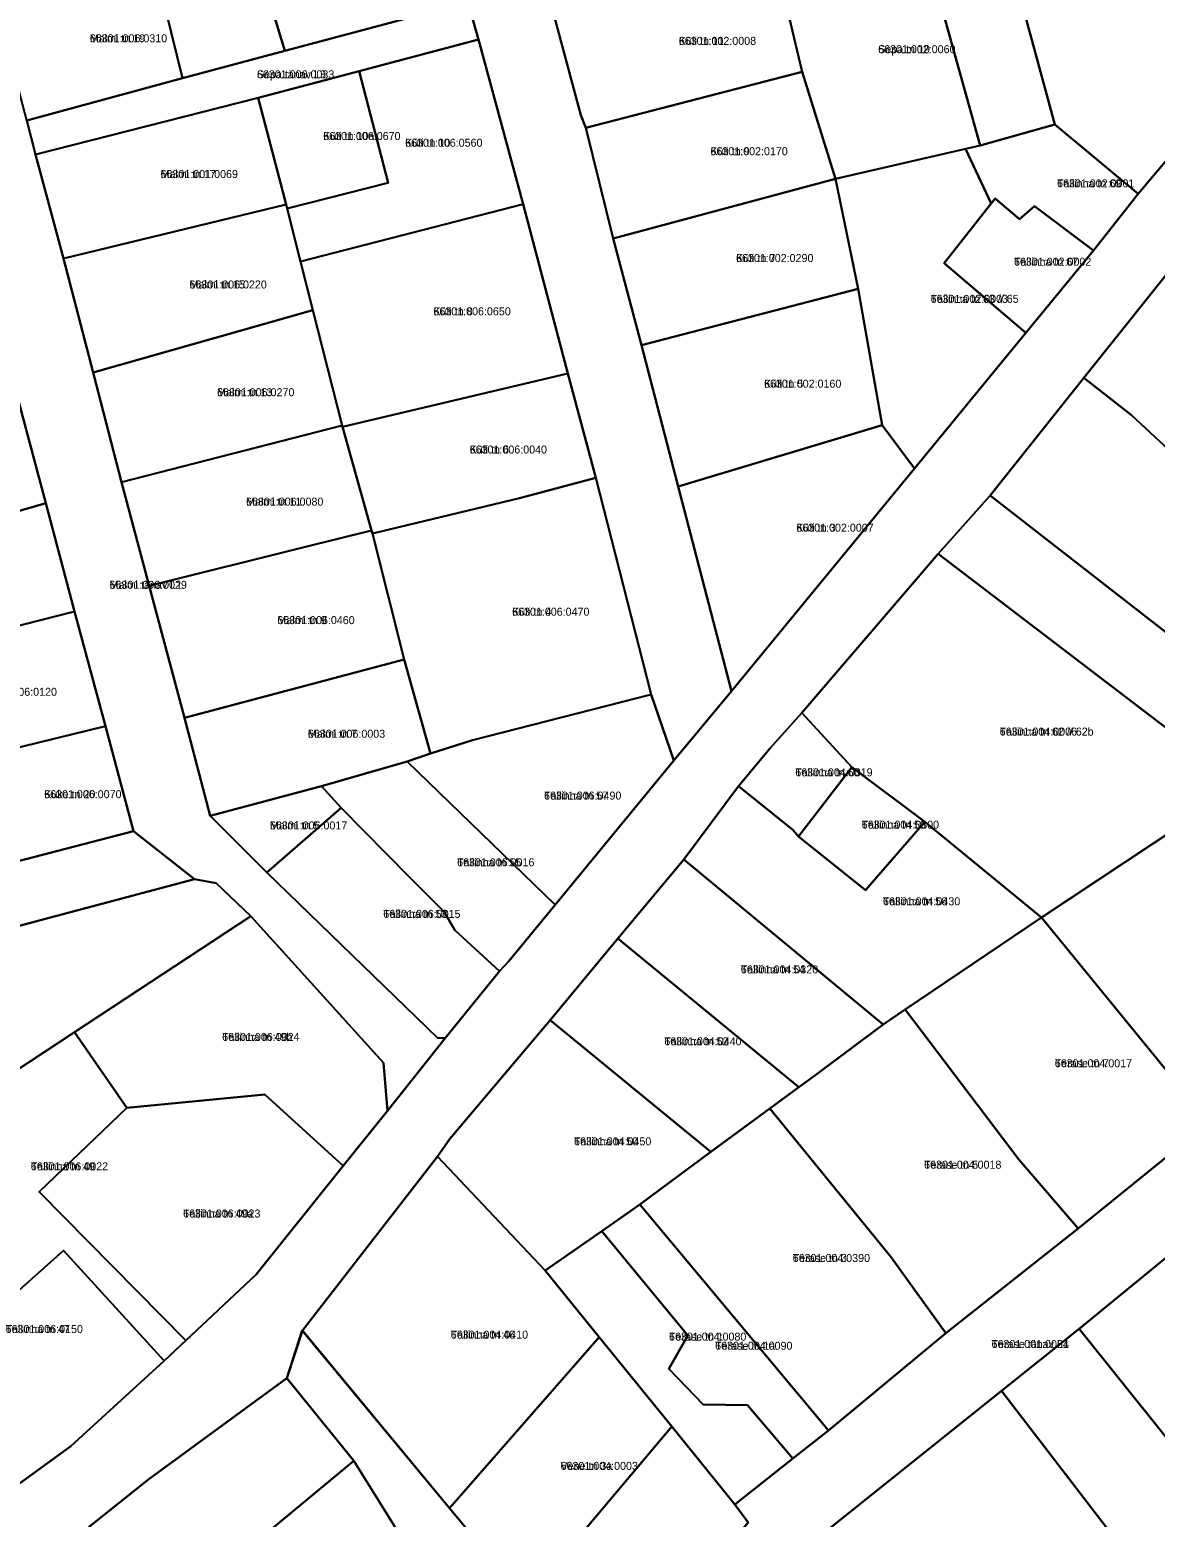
# Model space of a CAD drawing. Extents: x 632278 to 636344, y 6578401 to 6583362.
# Drawn here: x 634433.6 to 634644.7, y 6581866.9 to 6582145.8 of the extents above; entities that cross this region are included whole.
import ezdxf

# ---------------------------------------------------------------- set-up
doc = ezdxf.new("R2010")
doc.units = 0
for name, color, linetype in [('L_AADRESS', 7, 'Continuous'), ('PIIR', 7, 'Continuous'), ('TUNNUS', 7, 'Continuous')]:
    doc.layers.add(name, color=color, linetype=linetype)

msp = doc.modelspace()

# ---------------------------------------------------------------- linework, layer by layer
at = {"layer": 'PIIR'}
for points in [[(634482.01, 6582273.84), (634497.33, 6582277.18), (634507.5, 6582238.54), (634524.92, 6582174.47), (634530.36, 6582154.21), (634536.9, 6582129.81), (634537.89, 6582127.43), (634543.01, 6582106.64), (634548.28, 6582086.63), (634555.2, 6582060.13), (634565.22, 6582021.79), (634554.37, 6582008.75), (634550.12, 6582021.16), (634539.75, 6582061.77), (634534.51, 6582081.35), (634526.1, 6582113.12), (634517.75, 6582143.96), (634515.75, 6582150.96), (634510.3, 6582170.19), (634506.82, 6582183.37), (634504.01, 6582193.51), (634492.92, 6582234.47)], [(634515.75, 6582150.96), (634481.42, 6582141.82), (634475.39, 6582161.69), (634510.3, 6582170.19)], [(634600.44, 6582164.99), (634614.08, 6582168.85), (634619.66, 6582150.78), (634625.82, 6582128.04), (634611.81, 6582124.08)], [(634611.81, 6582124.08), (634584.7, 6582117.84), (634578.42, 6582137.89), (634573.58, 6582158.48), (634600.44, 6582164.99)], [(634456.96, 6582158.09), (634463.95, 6582159.56), (634468.75, 6582160.65), (634475.39, 6582161.69), (634481.42, 6582141.82), (634462.21, 6582136.73)], [(634456.96, 6582158.09), (634462.21, 6582136.73), (634433, 6582128.78), (634427.44, 6582149.82)], [(634532.03, 6582147.94), (634573.58, 6582158.48), (634578.42, 6582137.89), (634537.89, 6582127.43), (634536.9, 6582129.81)], [(634625.82, 6582128.04), (634619.66, 6582150.78), (634634.35, 6582155.12), (634643.77, 6582154.58), (634670.18, 6582151.52), (634667.16, 6582146.78), (634653.84, 6582129.72), (634641.46, 6582115.05)], [(634433, 6582128.78), (634462.21, 6582136.73), (634481.42, 6582141.82), (634515.75, 6582150.96), (634517.75, 6582143.96), (634495.33, 6582138.01), (634476.44, 6582133.05), (634434.65, 6582122.42)], [(634481.87, 6582112.27), (634500.78, 6582117.12), (634495.33, 6582138.01), (634517.75, 6582143.96), (634526.1, 6582113.12), (634484.38, 6582102.35)], [(634481.67, 6582113.05), (634476.44, 6582133.05), (634495.33, 6582138.01), (634500.78, 6582117.12), (634481.87, 6582112.27)], [(634537.89, 6582127.43), (634578.42, 6582137.89), (634584.7, 6582117.84), (634543.01, 6582106.64)], [(634439.93, 6582102.93), (634434.65, 6582122.42), (634476.44, 6582133.05), (634481.67, 6582113.05)], [(634613.87, 6582113.21), (634609.09, 6582123.45), (634611.81, 6582124.08), (634625.82, 6582128.04), (634641.46, 6582115.05), (634633.11, 6582104.43), (634622.05, 6582112.71), (634619.2, 6582110.28), (634614.63, 6582114.15)], [(634584.7, 6582117.84), (634609.09, 6582123.45), (634613.87, 6582113.21), (634605.06, 6582102.02), (634620.38, 6582088.96), (634599.5, 6582063.53), (634593.46, 6582071.65), (634588.97, 6582097.23)], [(634543.01, 6582106.64), (634584.7, 6582117.84), (634588.97, 6582097.23), (634548.28, 6582086.63)], [(634620.38, 6582088.96), (634605.06, 6582102.02), (634613.87, 6582113.21), (634614.63, 6582114.15), (634619.2, 6582110.28), (634622.05, 6582112.71), (634633.11, 6582104.43)], [(634481.87, 6582112.27), (634484.38, 6582102.35), (634486.69, 6582093.22), (634445.48, 6582081.5), (634439.93, 6582102.93), (634481.67, 6582113.05)], [(634492.23, 6582071.37), (634492.18, 6582071.58), (634486.69, 6582093.22), (634484.38, 6582102.35), (634526.1, 6582113.12), (634534.51, 6582081.35)], [(634650.44, 6582104.55), (634665.94, 6582089.46), (634671.9, 6582071.57), (634666.84, 6582067.2), (634665.01, 6582065.62), (634677.33, 6582051.32), (634679.16, 6582052.92), (634684.17, 6582057.32), (634699.78, 6582060.69), (634682.62, 6582038.21), (634666.05, 6582050.23), (634653.33, 6582061.35), (634640.2, 6582073.51), (634631.3, 6582080.56)], [(634588.97, 6582097.23), (634593.46, 6582071.65), (634555.2, 6582060.13), (634548.28, 6582086.63)], [(634445.48, 6582081.5), (634486.69, 6582093.22), (634492.18, 6582071.58), (634450.77, 6582060.94)], [(634497.64, 6582051.91), (634492.23, 6582071.37), (634534.51, 6582081.35), (634539.75, 6582061.77), (634525.44, 6582057.97), (634497.83, 6582051.33)], [(634613.71, 6582058.49), (634631.3, 6582080.56), (634640.2, 6582073.51), (634653.33, 6582061.35), (634666.05, 6582050.23), (634682.62, 6582038.21), (634665.06, 6582018.52)], [(634390.13, 6582066.59), (634430.99, 6582078.1), (634436.56, 6582057.04), (634395.75, 6582045.21)], [(634492.18, 6582071.58), (634492.23, 6582071.37), (634497.64, 6582051.91), (634485.26, 6582048.85), (634455.95, 6582041.55), (634450.77, 6582060.94)], [(634593.46, 6582071.65), (634599.5, 6582063.53), (634565.22, 6582021.79), (634555.2, 6582060.13)], [(634508.71, 6582010.09), (634503.81, 6582027.71), (634497.83, 6582051.33), (634525.44, 6582057.97), (634539.75, 6582061.77), (634550.12, 6582021.16), (634516.61, 6582012.59)], [(634657.44, 6582006.52), (634652.83, 6582010.24), (634603.94, 6582047.53), (634613.71, 6582058.49), (634665.06, 6582018.52), (634699.64, 6581977.29), (634708.82, 6581965.62), (634721.78, 6581949.85), (634735.56, 6581932.26), (634764.41, 6581896.09), (634775.13, 6581883.33), (634790.02, 6581865.68), (634816.43, 6581832.94), (634804.08, 6581823.17), (634777.49, 6581856.65), (634751.26, 6581889.92), (634737.61, 6581906.43), (634724.24, 6581923.68), (634711.06, 6581939.81), (634697.67, 6581956.75), (634688.59, 6581967.7), (634680.6, 6581977.83), (634660.03, 6582003.65)], [(634395.75, 6582045.21), (634436.56, 6582057.04), (634441.95, 6582036.73), (634400.67, 6582026.23)], [(634455.95, 6582041.55), (634485.26, 6582048.85), (634497.64, 6582051.91), (634497.83, 6582051.33), (634503.81, 6582027.71), (634462.61, 6582016.79)], [(634603.94, 6582047.53), (634652.83, 6582010.24), (634657.44, 6582006.52), (634660.03, 6582003.65), (634623.36, 6581979.36), (634601.44, 6581997.26), (634587.79, 6582007.55), (634578.39, 6582017.73)], [(634406.45, 6582005.09), (634400.67, 6582026.23), (634441.95, 6582036.73), (634447.76, 6582015.2), (634419.4, 6582008.26)], [(634467.38, 6581998.39), (634462.61, 6582016.79), (634503.81, 6582027.71), (634508.71, 6582010.09), (634504.33, 6582008.57), (634488.32, 6582003.96)], [(634508.71, 6582010.09), (634516.61, 6582012.59), (634550.12, 6582021.16), (634554.37, 6582008.75), (634532.1, 6581981.74), (634504.33, 6582008.57)], [(634566.51, 6582003.99), (634572.43, 6582011.11), (634578.39, 6582017.73), (634587.79, 6582007.55), (634577.76, 6581994.55), (634576.72, 6581995.76)], [(634447.76, 6582015.2), (634453.04, 6581995.54), (634424.86, 6581988.21), (634419.4, 6582008.26)], [(634504.33, 6582008.57), (634532.1, 6581981.74), (634523.4, 6581971.17), (634521.7, 6581969.3), (634513.32, 6581976.98), (634511.29, 6581980.41), (634504.78, 6581986.92), (634491.96, 6581999.91), (634488.32, 6582003.96)], [(634601.44, 6581997.26), (634590.34, 6581984.44), (634577.76, 6581994.55), (634587.79, 6582007.55)], [(634467.38, 6581998.39), (634488.32, 6582003.96), (634491.96, 6581999.91), (634478.04, 6581987.76)], [(634566.51, 6582003.99), (634576.72, 6581995.76), (634577.76, 6581994.55), (634590.34, 6581984.44), (634601.44, 6581997.26), (634623.36, 6581979.36), (634597.79, 6581962.1), (634593.61, 6581959.27), (634556.23, 6581990.21)], [(634646.78, 6581950.66), (634623.36, 6581979.36), (634660.03, 6582003.65), (634680.6, 6581977.83)], [(634491.96, 6581999.91), (634504.78, 6581986.92), (634511.29, 6581980.41), (634513.32, 6581976.98), (634521.7, 6581969.3), (634511.5, 6581956.74), (634510.06, 6581956.8), (634478.04, 6581987.76)], [(634273.04, 6581948.53), (634293.81, 6581953.85), (634305.5, 6581956.85), (634316.03, 6581959.82), (634338.34, 6581965.69), (634355.35, 6581970.3), (634370.29, 6581974.26), (634400.49, 6581981.96), (634424.86, 6581988.21), (634453.04, 6581995.54), (634464.5, 6581986.51), (634335, 6581952.07), (634276.05, 6581935.73)], [(634556.23, 6581990.21), (634593.61, 6581959.27), (634581.27, 6581950.01), (634577.8, 6581947.51), (634543.89, 6581975.39)], [(634335, 6581952.07), (634464.5, 6581986.51), (634468.53, 6581985.75), (634475.05, 6581979.62), (634441.97, 6581957.85), (634404.67, 6581933.3), (634389.2, 6581922.44), (634372.37, 6581910.73), (634355.89, 6581899.3), (634349.62, 6581894.94), (634347.96, 6581901.79), (634344.82, 6581914.73)], [(634475.05, 6581979.62), (634499.9, 6581952.11), (634500.66, 6581943.12), (634492.37, 6581932.78), (634477.66, 6581946.14), (634451.77, 6581943.65), (634441.97, 6581957.85)], [(634623.36, 6581979.36), (634646.78, 6581950.66), (634653.84, 6581940.16), (634630.24, 6581921.06), (634619.09, 6581933.95), (634597.79, 6581962.1)], [(634543.89, 6581975.39), (634577.8, 6581947.51), (634572.38, 6581943.56), (634561.34, 6581935.38), (634531.18, 6581960.1)], [(634545.08, 6581829.55), (634540.35, 6581834.86), (634549.04, 6581843.17), (634568.29, 6581865.93), (634565.82, 6581869.29), (634576.69, 6581877.91), (634583.39, 6581883.14), (634605.36, 6581901.38), (634630.24, 6581921.06), (634653.84, 6581940.16), (634688.59, 6581967.7), (634697.67, 6581956.75), (634664.21, 6581929.96), (634647.68, 6581916.34), (634630.37, 6581902.21), (634615.84, 6581890.6), (634577.32, 6581859.75), (634571.61, 6581855.04), (634560.16, 6581846.09)], [(634510.03, 6581934.55), (634512.34, 6581937.86), (634531.18, 6581960.1), (634561.34, 6581935.38), (634547.98, 6581925.55), (634540.85, 6581920.5), (634530.25, 6581913.14)], [(634597.79, 6581962.1), (634619.09, 6581933.95), (634630.24, 6581921.06), (634605.36, 6581901.38), (634595.09, 6581915.73), (634572.38, 6581943.56), (634577.8, 6581947.51), (634581.27, 6581950.01), (634593.61, 6581959.27)], [(634441.97, 6581957.85), (634451.77, 6581943.65), (634435.34, 6581927.88), (634462.84, 6581900.03), (634458.8, 6581896.24), (634439.92, 6581916.91), (634427.42, 6581905.76), (634404.67, 6581933.3)], [(634477.66, 6581946.14), (634492.37, 6581932.78), (634476.03, 6581912.43), (634462.84, 6581900.03), (634435.34, 6581927.88), (634451.77, 6581943.65)], [(634561.34, 6581935.38), (634572.38, 6581943.56), (634595.09, 6581915.73), (634605.36, 6581901.38), (634583.39, 6581883.14), (634547.98, 6581925.55)], [(634389.2, 6581922.44), (634404.67, 6581933.3), (634427.42, 6581905.76), (634439.92, 6581916.91), (634458.8, 6581896.24), (634441.28, 6581880.2), (634426.5, 6581869.55)], [(634484.7, 6581901.91), (634510.03, 6581934.55), (634530.25, 6581913.14), (634540.36, 6581900.67), (634512.3, 6581868.6)], [(634576.69, 6581877.91), (634568.16, 6581887.92), (634559.85, 6581888), (634553.44, 6581894.72), (634557, 6581900.98), (634540.85, 6581920.5), (634547.98, 6581925.55), (634583.39, 6581883.14)], [(634530.25, 6581913.14), (634540.85, 6581920.5), (634557, 6581900.98), (634553.44, 6581894.72), (634559.85, 6581888), (634568.16, 6581887.92), (634576.69, 6581877.91), (634565.82, 6581869.29), (634553.97, 6581883.89), (634540.36, 6581900.67)], [(634647.68, 6581916.34), (634671.64, 6581887.28), (634655.05, 6581873.59), (634654.08, 6581872.66), (634630.37, 6581902.21)], [(634512.3, 6581868.6), (634540.36, 6581900.67), (634553.97, 6581883.89), (634526.64, 6581851.4)], [(634455.88, 6581874.06), (634481.77, 6581892.96), (634494.38, 6581877.44), (634477.89, 6581863.85), (634491.85, 6581846.24), (634472.24, 6581830.74), (634444.78, 6581865.18)], [(634643.79, 6581854.2), (634602.63, 6581822.71), (634601.51, 6581824.51), (634595.58, 6581833.06), (634595.19, 6581833.66), (634577.32, 6581859.75), (634615.84, 6581890.6)], [(634526.64, 6581851.4), (634553.97, 6581883.89), (634565.82, 6581869.29), (634568.29, 6581865.93), (634549.04, 6581843.17), (634540.35, 6581834.86)], [(634477.89, 6581863.85), (634494.38, 6581877.44), (634506.52, 6581857.93), (634491.85, 6581846.24)]]:
    msp.add_lwpolyline(points, close=True, dxfattribs=at)
for points in [[(634426.5, 6581869.55), (634441.28, 6581880.2), (634458.8, 6581896.24), (634462.84, 6581900.03), (634476.03, 6581912.43), (634492.37, 6581932.78), (634500.66, 6581943.12), (634511.5, 6581956.74), (634521.7, 6581969.3), (634523.4, 6581971.17), (634532.1, 6581981.74), (634554.37, 6582008.75), (634565.22, 6582021.79), (634599.5, 6582063.53), (634620.38, 6582088.96), (634633.11, 6582104.43), (634641.46, 6582115.05), (634653.84, 6582129.72)], [(634433, 6582128.78), (634434.65, 6582122.42), (634439.93, 6582102.93), (634445.48, 6582081.5), (634450.77, 6582060.94), (634455.95, 6582041.55), (634462.61, 6582016.79), (634467.38, 6581998.39), (634478.04, 6581987.76), (634510.06, 6581956.8), (634511.5, 6581956.74), (634500.66, 6581943.12), (634499.9, 6581952.11), (634475.05, 6581979.62), (634468.53, 6581985.75), (634464.5, 6581986.51), (634453.04, 6581995.54), (634447.76, 6582015.2), (634441.95, 6582036.73), (634436.56, 6582057.04), (634430.99, 6582078.1)], [(634650.44, 6582104.55), (634631.3, 6582080.56), (634613.71, 6582058.49), (634603.94, 6582047.53), (634578.39, 6582017.73), (634572.43, 6582011.11), (634566.51, 6582003.99), (634556.23, 6581990.21), (634543.89, 6581975.39), (634531.18, 6581960.1), (634512.34, 6581937.86), (634510.03, 6581934.55), (634484.7, 6581901.91), (634481.77, 6581892.96), (634455.88, 6581874.06), (634444.78, 6581865.18), (634426.56, 6581852.55)], [(634619.36, 6581722.14), (634601.75, 6581744.09), (634580.89, 6581769.41), (634561.44, 6581793.86), (634540.52, 6581819.75), (634533.2, 6581825.04), (634506.51, 6581857.94), (634494.38, 6581877.44), (634481.77, 6581892.97), (634484.69, 6581901.92), (634512.29, 6581868.61), (634526.64, 6581851.4), (634540.35, 6581834.86), (634545.08, 6581829.55), (634567.3, 6581800.98), (634581.06, 6581784.32), (634594.33, 6581767.24), (634621.98, 6581733.46), (634649.14, 6581699.56)], [(634755.08, 6581717.15), (634742.28, 6581732.68), (634719.07, 6581760.66), (634705.15, 6581777.74), (634678.08, 6581811.31), (634660.64, 6581832.59), (634643.79, 6581854.2), (634615.84, 6581890.6), (634630.37, 6581902.21), (634654.08, 6581872.66), (634655.05, 6581873.59), (634666.85, 6581859.15), (634679.37, 6581843.48), (634691.79, 6581827.86), (634704.31, 6581811.89), (634720.9, 6581791.1), (634734.12, 6581774.42), (634740.15, 6581772.43), (634749.69, 6581755.05), (634785.04, 6581712.01)]]:
    msp.add_lwpolyline(points, dxfattribs=at)

# ---------------------------------------------------------------- texts
at = {"layer": 'L_AADRESS'}
for s, p in [('Malmi tn 19', (634444.84, 6582143.44)), ('Küti tn 11', (634555.3, 6582142.96)), ('Sepa tn 19', (634592.7, 6582141.4)), ('Sepa tänav L3', (634476.18, 6582136.69)), ('Küti tn 10a', (634488.61, 6582125.12)), ('Küti tn 10', (634503.98, 6582123.86)), ('Küti tn 9', (634561.24, 6582122.27)), ('Malmi tn 17', (634458.11, 6582117.99)), ('Tallinna tn 69', (634626.25, 6582116.24)), ('Küti tn 7', (634566.05, 6582102.24)), ('Tallinna tn 67', (634618.17, 6582101.55)), ('Malmi tn 15', (634463.53, 6582097.28)), ('Tallinna tn 63 // 65', (634602.54, 6582094.59)), ('Küti tn 8', (634509.28, 6582092.25)), ('Küti tn 5', (634571.29, 6582078.68)), ('Malmi tn 13', (634468.7, 6582077.08)), ('Küti tn 6', (634516.08, 6582066.34)), ('Malmi tn 11', (634474.14, 6582056.57)), ('Küti tn 3', (634577.35, 6582051.68)), ('Malmi tänav L1', (634448.54, 6582040.97)), ('Malmi tn 9', (634480.01, 6582034.35)), ('Küti tn 4', (634524.04, 6582035.93)), ('Malmi tn 7', (634485.73, 6582013.05)), ('Tallinna tn 62 // 62b', (634615.49, 6582013.45)), ('Tallinna tn 60', (634577.15, 6582005.81)), ('Kuke tn 20', (634436.28, 6582001.71)), ('Tallinna tn 57', (634530.03, 6582001.45)), ('Malmi tn 5', (634478.62, 6581995.86)), ('Tallinna tn 58', (634589.61, 6581996)), ('Tallinna tn 55', (634513.72, 6581988.94)), ('Tallinna tn 56', (634593.59, 6581981.63)), ('Tallinna tn 53', (634499.87, 6581979.27)), ('Tallinna tn 54', (634566.93, 6581968.86)), ('Tallinna tn 49b', (634469.66, 6581956.2)), ('Tallinna tn 52', (634552.58, 6581955.38)), ('Terase tn 7', (634625.82, 6581951.26)), ('Tallinna tn 50', (634535.65, 6581936.62)), ('Tallinna tn 49', (634433.76, 6581931.93)), ('Terase tn 5', (634601.31, 6581932.24)), ('Tallinna tn 49a', (634462.33, 6581923.09)), ('Terase tn 3', (634576.67, 6581914.75)), ('Tallinna tn 47', (634429.04, 6581901.43)), ('Tallinna tn 46', (634512.53, 6581900.38)), ('Terase tn 1', (634553.47, 6581900.01)), ('Terase tn 1a', (634562.12, 6581898.3)), ('Terase tänav L1', (634613.96, 6581898.62)), ('Vene tn 3a', (634533.13, 6581875.77))]:
    msp.add_text(s, height=1.5, dxfattribs=at).set_placement(p)
at = {"layer": 'TUNNUS'}
for s, p in [('66301:006:0310', (634444.84, 6582143.44)), ('66301:002:0008', (634555.3, 6582142.96)), ('66301:002:0060', (634592.7, 6582141.4)), ('66301:006:0033', (634476.18, 6582136.69)), ('66301:006:0670', (634488.61, 6582125.12)), ('66301:006:0560', (634503.98, 6582123.86)), ('66301:002:0170', (634561.24, 6582122.27)), ('66301:001:0069', (634458.11, 6582117.99)), ('66301:002:0001', (634626.25, 6582116.24)), ('66301:002:0290', (634566.05, 6582102.24)), ('66301:002:0002', (634618.17, 6582101.55)), ('66301:006:0220', (634463.53, 6582097.28)), ('66301:002:0003', (634602.54, 6582094.59)), ('66301:006:0650', (634509.28, 6582092.25)), ('66301:002:0160', (634571.29, 6582078.68)), ('66301:006:0270', (634468.7, 6582077.08)), ('66301:006:0040', (634516.08, 6582066.34)), ('66301:006:0080', (634474.14, 6582056.57)), ('66301:002:0007', (634577.35, 6582051.68)), ('66301:006:0029', (634448.54, 6582040.97)), ('66301:006:0460', (634480.01, 6582034.35)), ('66301:006:0470', (634524.04, 6582035.93)), ('66301:006:0120', (634424.17, 6582020.91)), ('66301:006:0003', (634485.73, 6582013.05)), ('66301:004:0006', (634615.49, 6582013.45)), ('66301:004:0019', (634577.15, 6582005.81)), ('66301:006:0070', (634436.28, 6582001.71)), ('66301:006:0490', (634530.03, 6582001.45)), ('66301:006:0017', (634478.62, 6581995.86)), ('66301:004:0300', (634589.61, 6581996)), ('66301:006:0016', (634513.72, 6581988.94)), ('66301:004:0430', (634593.59, 6581981.63)), ('66301:006:0015', (634499.87, 6581979.27)), ('66301:004:0320', (634566.93, 6581968.86)), ('66301:006:0024', (634469.66, 6581956.2)), ('66301:004:0440', (634552.58, 6581955.38)), ('66301:004:0017', (634625.82, 6581951.26)), ('66301:004:0450', (634535.65, 6581936.62)), ('66301:006:0022', (634433.76, 6581931.93)), ('66301:004:0018', (634601.31, 6581932.24)), ('66301:006:0023', (634462.33, 6581923.09)), ('66301:004:0390', (634576.67, 6581914.75)), ('66301:006:0150', (634429.04, 6581901.43)), ('66301:004:0410', (634512.53, 6581900.38)), ('66301:004:0080', (634553.47, 6581900.01)), ('66301:004:0090', (634562.12, 6581898.3)), ('66301:001:0064', (634613.96, 6581898.62)), ('66301:004:0003', (634533.13, 6581875.77))]:
    msp.add_text(s, height=1.5, dxfattribs=at).set_placement(p)

doc.saveas('drawing.dxf')
